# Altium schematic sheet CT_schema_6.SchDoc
size 248 x 146 mm
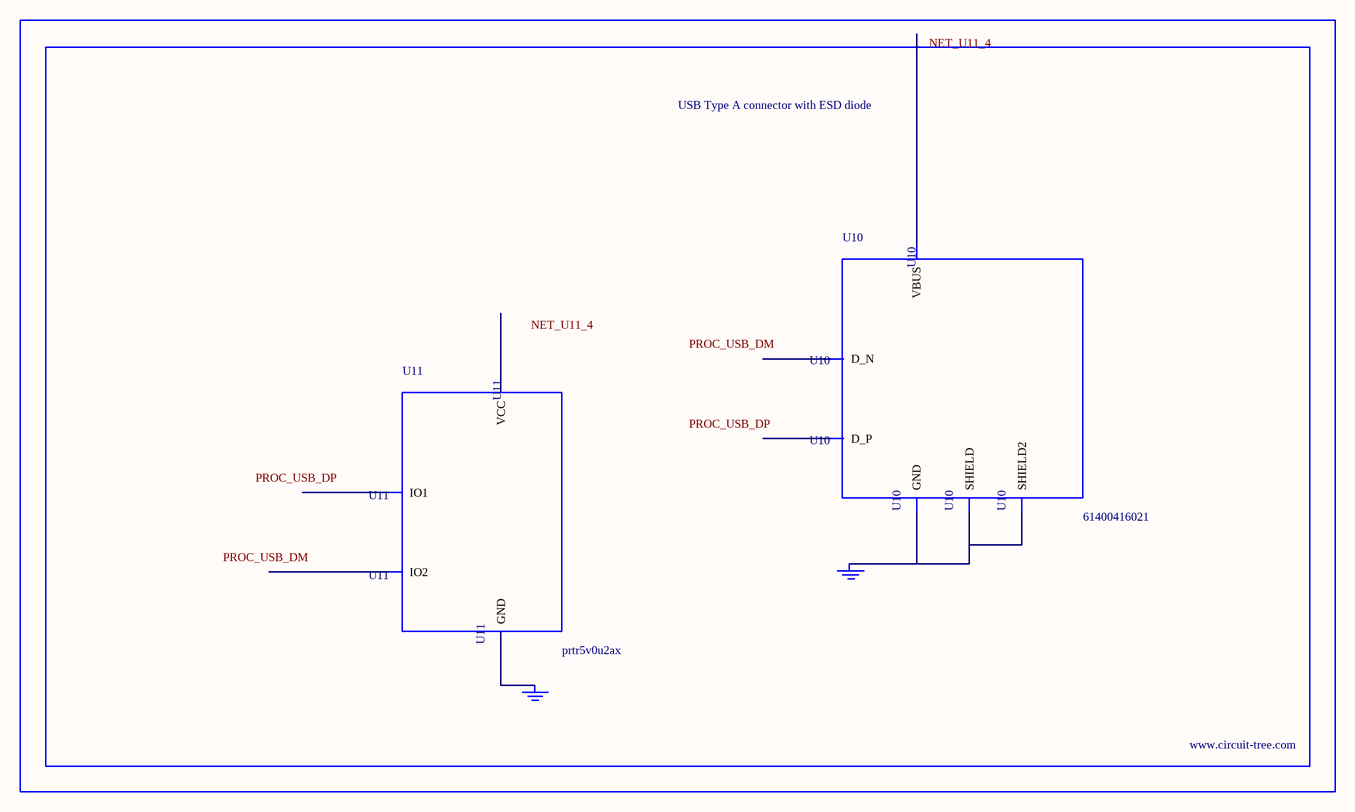
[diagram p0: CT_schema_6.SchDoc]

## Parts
BORDER5  (no value)
GND_INSTANCE_5_0  (no value)
GND_INSTANCE_5_1  (no value)
U10  61400416021  [USB-A-H]
U11  prtr5v0u2ax  [SOT143B]

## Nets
NetGND_INSTANCE_5_0_0: GND_INSTANCE_5_0.0(GND) U10.4(GND) U10.5(SHIELD) U10.6(SHIELD2)
NetGND_INSTANCE_5_1_0: GND_INSTANCE_5_1.0(GND) U11.1(GND)

Not connected (* = marked no-connect by the designer): U10 1(VBUS) 2(D_N) 3(D_P); U11 2(IO1) 3(IO2) 4(VCC)

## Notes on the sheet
- Labels drawn without touching a wire or pin: NET_U11_4, PROC_USB_DM, PROC_USB_DP

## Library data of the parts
BORDER5 = BORDER_PAGE5
GND_INSTANCE_5_0 GND_INSTANCE_5_1 = GND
